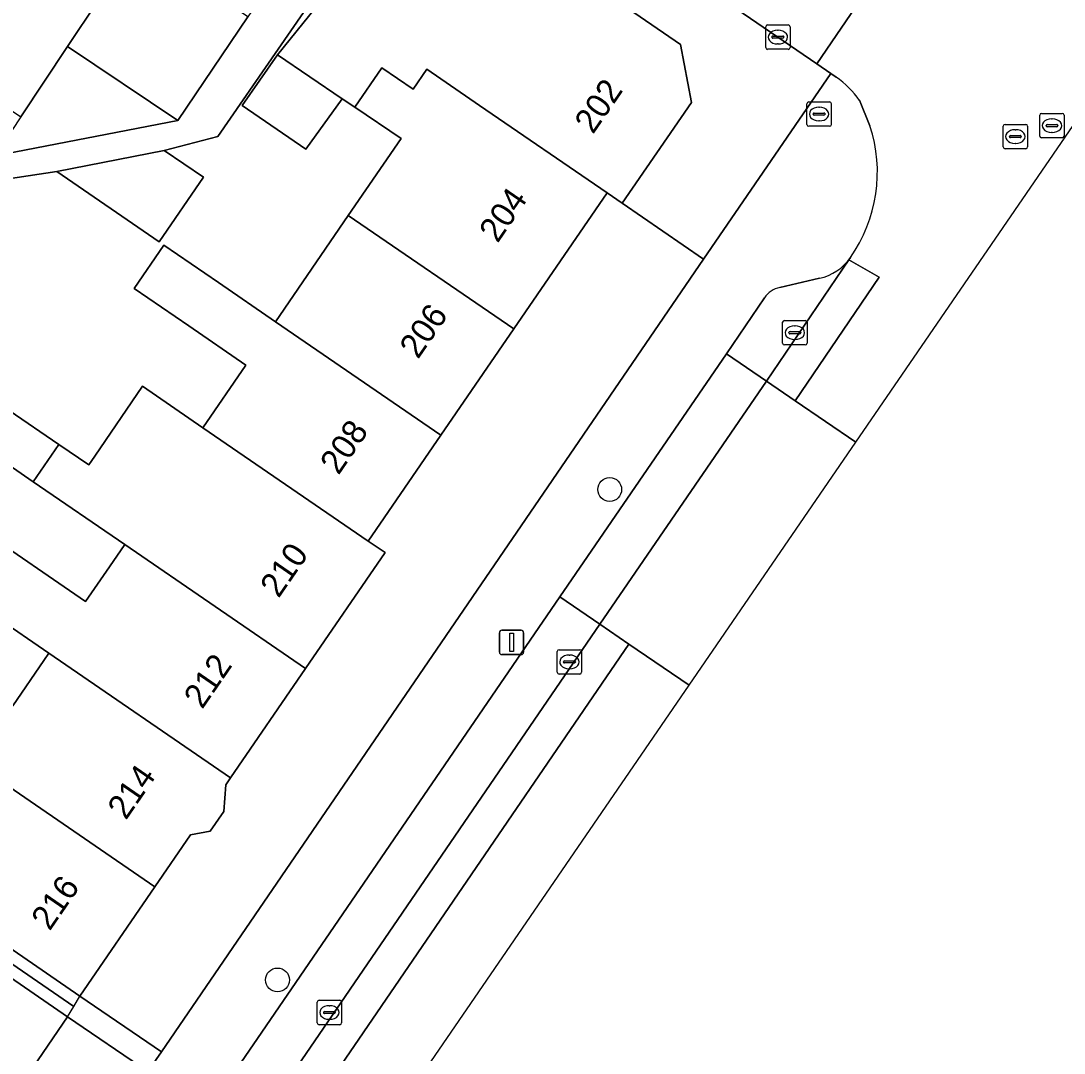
# Model space of a CAD drawing. Extents: x 159664 to 160323, y 385312 to 386115.
# Drawn here: x 160092.11 to 160134.93, y 385438.49 to 385480.85 of the extents above; entities that cross this region are included whole.
import ezdxf

# ---------------------------------------------------------------- set-up
doc = ezdxf.new("R2010")
doc.units = 0
for name, color, linetype in [('IMGEO_Boom', 7, 'Continuous'), ('IMGEO_Brandkraan', 7, 'Continuous'), ('IMGEO_Erf', 7, 'Continuous'), ('IMGEO_Kolk', 7, 'Continuous'), ('IMGEO_Lichtmast', 7, 'Continuous'), ('IMGEO_Pand', 7, 'Continuous'), ('IMGEO_Pand_nummerreeks', 7, 'Continuous'), ('IMGEO_Pand_overbouw', 7, 'Continuous'), ('IMGEO_Parkeervlak_open', 7, 'Continuous'), ('IMGEO_Rijbaan_lokaal_gesloten', 7, 'Continuous'), ('IMGEO_Rijbaan_lokaal_open', 7, 'Continuous'), ('IMGEO_Rioolput', 7, 'Continuous'), ('IMGEO_Voetpad_open', 7, 'Continuous')]:
    doc.layers.add(name, color=color, linetype=linetype)

msp = doc.modelspace()

# ---------------------------------------------------------------- linework, layer by layer
at = {"layer": 'IMGEO_Boom'}
for centre in [(160116.28, 385461.618), (160102.646, 385441.491)]:
    msp.add_circle(centre, 0.489, dxfattribs=at)
at = {"layer": 'IMGEO_Brandkraan'}
for p, q in [((160124.376, 385476.598), (160124.376, 385477.45)), ((160124.451, 385477.524), (160125.303, 385477.524)), ((160125.377, 385477.45), (160125.377, 385476.598)), ((160124.635, 385477.018), (160124.635, 385477.03)), ((160125.073, 385476.981), (160124.675, 385476.981)), ((160124.678, 385477.067), (160125.076, 385477.067)), ((160124.864, 385477.304), (160124.889, 385477.304)), ((160125.119, 385477.03), (160125.119, 385477.018)), ((160125.303, 385476.524), (160124.451, 385476.524)), ((160124.887, 385476.744), (160124.862, 385476.744))]:
    msp.add_line(p, q, dxfattribs=at)
for points in [[(160124.376, 385476.598), (160124.376, 385477.45)], [(160124.451, 385477.524), (160125.303, 385477.524)], [(160125.377, 385477.45), (160125.377, 385476.598)], [(160125.303, 385476.524), (160124.451, 385476.524)]]:
    msp.add_lwpolyline(points, dxfattribs=at)
for centre, radius, start, end in [((160124.453, 385477.448), 0.0765, 91.552, 178.448), ((160124.453, 385477.448), 0.0765, 91.552, 178.448), ((160125.301, 385477.448), 0.0765, 1.552, 88.448), ((160125.301, 385477.448), 0.0765, 1.552, 88.448), ((160124.675, 385477.027), 0.0403, 85.8775, 175.7526), ((160124.672, 385477.017), 0.0366, 178.938, 274.7102), ((160125.076, 385477.024), 0.043, 264.8664, 352.4533), ((160125.08, 385477.029), 0.0386, 1.7309, 96.639), ((160124.453, 385476.6), 0.0765, 181.552, 268.448), ((160124.453, 385476.6), 0.0765, 181.552, 268.448), ((160125.301, 385476.6), 0.0765, 271.552, 358.448), ((160125.301, 385476.6), 0.0765, 271.552, 358.448)]:
    msp.add_arc(centre, radius, start, end, dxfattribs=at)
for centre, major_axis, ratio, start_param, end_param in [((160124.863, 385477.024), (-0.387, 0.002), 0.722429, 4.712389, 7.853982), ((160124.888, 385477.024), (-0.39, 0.002), 0.717154, 1.570796, 4.712389)]:
    msp.add_ellipse(centre, major_axis=major_axis, ratio=ratio, start_param=start_param, end_param=end_param, dxfattribs=at)
at = {"layer": 'IMGEO_Erf'}
for points in [[(160095.272, 385481.662), (160090.71, 385484.694), (160091.519, 385485.911), (160089.549, 385487.221), (160090.42, 385488.53), (160087.729, 385490.367), (160084.661, 385492.46), (160083.962, 385491.435), (160082.623, 385489.472), (160084.288, 385488.335), (160084.678, 385488.927), (160086.246, 385487.894), (160084.943, 385485.918), (160089.252, 385482.91), (160087.283, 385480.142), (160092.11, 385476.904), (160094.031, 385479.795)], [(160120.131, 385471.065), (160116.798, 385473.364), (160116.172, 385473.793), (160112.341, 385468.206), (160109.353, 385463.849), (160106.372, 385459.503), (160107.06, 385459.031), (160103.796, 385454.271), (160100.72, 385449.785), (160100.525, 385449.501), (160100.44, 385448.404), (160099.89, 385447.602), (160099.078, 385447.451), (160097.614, 385445.316), (160094.537, 385440.829), (160097.88, 385438.542)], [(160097.326, 385437.733), (160094.034, 385439.985), (160090.961, 385435.505), (160087.888, 385431.024), (160084.816, 385426.545), (160081.744, 385422.066), (160085.057, 385419.799)]]:
    msp.add_lwpolyline(points, close=True, dxfattribs=at)
for points in [[(160105.155, 385483.28), (160100.197, 385476.099), (160097.997, 385475.531), (160099.604, 385474.434), (160097.786, 385471.782), (160093.588, 385474.662), (160088.142, 385473.845)], [(160091.641, 385464.862), (160093.676, 385463.466), (160094.9, 385462.626), (160095.144, 385462.982), (160097.112, 385465.852), (160099.589, 385464.154), (160101.352, 385466.723), (160099.003, 385468.334), (160096.759, 385469.873), (160097.977, 385471.647), (160100.221, 385470.109), (160102.566, 385468.503), (160105.553, 385472.86), (160107.72, 385476.019), (160105.824, 385477.303), (160105.305, 385477.655), (160103.816, 385475.587), (160101.193, 385477.369), (160102.652, 385479.452), (160105.528, 385483.033)], [(160090.421, 385460.003), (160094.77, 385457.02), (160095.751, 385458.451), (160096.375, 385459.361), (160092.625, 385461.933), (160090.59, 385463.329)], [(160091.787, 385452.746), (160093.063, 385454.606), (160093.264, 385454.898), (160088.949, 385457.857)]]:
    msp.add_lwpolyline(points, dxfattribs=at)
at = {"layer": 'IMGEO_Kolk'}
for p, q in [((160122.682, 385479.755), (160122.682, 385480.607)), ((160122.757, 385480.681), (160123.609, 385480.681)), ((160123.17, 385480.461), (160123.195, 385480.461)), ((160123.683, 385480.607), (160123.683, 385479.755)), ((160122.941, 385480.175), (160122.941, 385480.187)), ((160123.379, 385480.138), (160122.981, 385480.138)), ((160122.984, 385480.224), (160123.382, 385480.224)), ((160123.193, 385479.901), (160123.168, 385479.901)), ((160123.425, 385480.187), (160123.425, 385480.175)), ((160123.609, 385479.681), (160122.757, 385479.681)), ((160123.379, 385467.627), (160123.379, 385468.479)), ((160123.454, 385468.553), (160124.306, 385468.553)), ((160123.867, 385468.333), (160123.892, 385468.333)), ((160124.38, 385468.479), (160124.38, 385467.627)), ((160123.638, 385468.047), (160123.638, 385468.059)), ((160124.076, 385468.01), (160123.678, 385468.01)), ((160123.681, 385468.096), (160124.079, 385468.096)), ((160124.122, 385468.059), (160124.122, 385468.047)), ((160124.306, 385467.553), (160123.454, 385467.553)), ((160123.89, 385467.773), (160123.865, 385467.773)), ((160114.128, 385454.118), (160114.128, 385454.97)), ((160114.203, 385455.044), (160115.055, 385455.044)), ((160114.616, 385454.824), (160114.641, 385454.824)), ((160115.129, 385454.97), (160115.129, 385454.118)), ((160114.387, 385454.538), (160114.387, 385454.55)), ((160114.825, 385454.501), (160114.427, 385454.501)), ((160114.43, 385454.587), (160114.828, 385454.587)), ((160114.639, 385454.264), (160114.614, 385454.264)), ((160114.871, 385454.55), (160114.871, 385454.538)), ((160115.055, 385454.044), (160114.203, 385454.044)), ((160104.279, 385439.73), (160104.279, 385440.582)), ((160104.354, 385440.656), (160105.206, 385440.656)), ((160105.28, 385440.582), (160105.28, 385439.73)), ((160104.538, 385440.15), (160104.538, 385440.162)), ((160104.976, 385440.113), (160104.578, 385440.113)), ((160104.581, 385440.199), (160104.979, 385440.199)), ((160104.767, 385440.436), (160104.792, 385440.436)), ((160105.022, 385440.162), (160105.022, 385440.15)), ((160105.206, 385439.656), (160104.354, 385439.656)), ((160104.79, 385439.876), (160104.765, 385439.876))]:
    msp.add_line(p, q, dxfattribs=at)
for points in [[(160122.682, 385479.755), (160122.682, 385480.607)], [(160122.757, 385480.681), (160123.609, 385480.681)], [(160123.683, 385480.607), (160123.683, 385479.755)], [(160123.609, 385479.681), (160122.757, 385479.681)], [(160123.379, 385467.627), (160123.379, 385468.479)], [(160123.454, 385468.553), (160124.306, 385468.553)], [(160124.38, 385468.479), (160124.38, 385467.627)], [(160124.306, 385467.553), (160123.454, 385467.553)], [(160114.128, 385454.118), (160114.128, 385454.97)], [(160114.203, 385455.044), (160115.055, 385455.044)], [(160115.129, 385454.97), (160115.129, 385454.118)], [(160115.055, 385454.044), (160114.203, 385454.044)], [(160104.279, 385439.73), (160104.279, 385440.582)], [(160104.354, 385440.656), (160105.206, 385440.656)], [(160105.28, 385440.582), (160105.28, 385439.73)], [(160105.206, 385439.656), (160104.354, 385439.656)]]:
    msp.add_lwpolyline(points, dxfattribs=at)
for centre, radius, start, end in [((160122.759, 385480.605), 0.0765, 91.552, 178.448), ((160122.759, 385480.605), 0.0765, 91.552, 178.448), ((160123.607, 385480.605), 0.0765, 1.552, 88.448), ((160123.607, 385480.605), 0.0765, 1.552, 88.448), ((160122.981, 385480.184), 0.0403, 85.8775, 175.7526), ((160122.978, 385480.174), 0.0366, 178.938, 274.7102), ((160123.382, 385480.181), 0.043, 264.8664, 352.4533), ((160123.386, 385480.186), 0.0386, 1.7309, 96.639), ((160122.759, 385479.757), 0.0765, 181.552, 268.448), ((160122.759, 385479.757), 0.0765, 181.552, 268.448), ((160123.607, 385479.757), 0.0765, 271.552, 358.448), ((160123.607, 385479.757), 0.0765, 271.552, 358.448), ((160123.456, 385468.477), 0.0765, 91.552, 178.448), ((160123.456, 385468.477), 0.0765, 91.552, 178.448), ((160124.304, 385468.477), 0.0765, 1.552, 88.448), ((160124.304, 385468.477), 0.0765, 1.552, 88.448), ((160123.678, 385468.056), 0.0403, 85.8775, 175.7526), ((160123.675, 385468.046), 0.0366, 178.938, 274.7102), ((160124.079, 385468.053), 0.043, 264.8664, 352.4533), ((160124.083, 385468.058), 0.0386, 1.7309, 96.639), ((160123.456, 385467.629), 0.0765, 181.552, 268.448), ((160123.456, 385467.629), 0.0765, 181.552, 268.448), ((160124.304, 385467.629), 0.0765, 271.552, 358.448), ((160124.304, 385467.629), 0.0765, 271.552, 358.448), ((160114.205, 385454.968), 0.0765, 91.552, 178.448), ((160114.205, 385454.968), 0.0765, 91.552, 178.448), ((160115.053, 385454.968), 0.0765, 1.552, 88.448), ((160115.053, 385454.968), 0.0765, 1.552, 88.448), ((160114.427, 385454.547), 0.0403, 85.8775, 175.7526), ((160114.424, 385454.537), 0.0366, 178.938, 274.7102), ((160114.828, 385454.544), 0.043, 264.8664, 352.4533), ((160114.832, 385454.549), 0.0386, 1.7309, 96.639), ((160114.205, 385454.12), 0.0765, 181.552, 268.448), ((160114.205, 385454.12), 0.0765, 181.552, 268.448), ((160115.053, 385454.12), 0.0765, 271.552, 358.448), ((160115.053, 385454.12), 0.0765, 271.552, 358.448), ((160104.356, 385440.58), 0.0765, 91.552, 178.448), ((160104.356, 385440.58), 0.0765, 91.552, 178.448), ((160105.204, 385440.58), 0.0765, 1.552, 88.448), ((160105.204, 385440.58), 0.0765, 1.552, 88.448), ((160104.578, 385440.159), 0.0403, 85.8775, 175.7526), ((160104.575, 385440.149), 0.0366, 178.938, 274.7102), ((160104.979, 385440.156), 0.043, 264.8664, 352.4533), ((160104.983, 385440.161), 0.0386, 1.7309, 96.639), ((160104.356, 385439.732), 0.0765, 181.552, 268.448), ((160104.356, 385439.732), 0.0765, 181.552, 268.448), ((160105.204, 385439.732), 0.0765, 271.552, 358.448), ((160105.204, 385439.732), 0.0765, 271.552, 358.448)]:
    msp.add_arc(centre, radius, start, end, dxfattribs=at)
for centre, major_axis, ratio, start_param, end_param in [((160123.169, 385480.181), (-0.387, 0.002), 0.722429, 4.712389, 7.853982), ((160123.194, 385480.181), (-0.39, 0.002), 0.717154, 1.570796, 4.712389), ((160123.866, 385468.053), (-0.387, 0.002), 0.722429, 4.712389, 7.853982), ((160123.891, 385468.053), (-0.39, 0.002), 0.717154, 1.570796, 4.712389), ((160114.615, 385454.544), (-0.387, 0.002), 0.722429, 4.712389, 7.853982), ((160114.64, 385454.544), (-0.39, 0.002), 0.717154, 1.570796, 4.712389), ((160104.766, 385440.156), (-0.387, 0.002), 0.722429, 4.712389, 7.853982), ((160104.791, 385440.156), (-0.39, 0.002), 0.717154, 1.570796, 4.712389)]:
    msp.add_ellipse(centre, major_axis=major_axis, ratio=ratio, start_param=start_param, end_param=end_param, dxfattribs=at)
at = {"layer": 'IMGEO_Lichtmast'}
for p, q in [((160111.757, 385454.941), (160111.757, 385455.741)), ((160111.757, 385455.741), (160111.757, 385454.941)), ((160111.857, 385455.841), (160112.647, 385455.841)), ((160112.647, 385455.841), (160111.857, 385455.841)), ((160112.747, 385455.741), (160112.747, 385454.941)), ((160112.747, 385454.941), (160112.747, 385455.741)), ((160112.647, 385454.841), (160111.857, 385454.841)), ((160111.857, 385454.841), (160112.647, 385454.841))]:
    msp.add_line(p, q, dxfattribs=at)
msp.add_lwpolyline([(160112.177, 385455.716), (160112.327, 385455.716), (160112.327, 385454.966), (160112.177, 385454.966), (160112.177, 385455.716)], dxfattribs=at)
for centre, start, end in [((160111.857, 385455.741), 90, 180), ((160111.857, 385455.741), 90, 180), ((160112.647, 385455.741), 0, 90), ((160112.647, 385455.741), 360, 90), ((160111.857, 385454.941), 180, 270), ((160111.857, 385454.941), 180, 270), ((160112.647, 385454.941), 270, 0), ((160112.647, 385454.941), 270, 0)]:
    msp.add_arc(centre, 0.1, start, end, dxfattribs=at)
at = {"layer": 'IMGEO_Pand'}
for points in [[(160119.187, 385479.884), (160108.429, 385487.262), (160105.601, 385483.139), (160105.528, 385483.033), (160102.652, 385479.452), (160105.305, 385477.655), (160105.824, 385477.303), (160106.935, 385478.924), (160108.219, 385478.044), (160108.779, 385478.861), (160110.94, 385477.38), (160116.172, 385473.793), (160116.798, 385473.364), (160119.632, 385477.496)], [(160101.434, 385481.016), (160096.899, 385484.11), (160095.272, 385481.662), (160094.031, 385479.795), (160098.556, 385476.767)], [(160094.031, 385479.795), (160092.11, 385476.904), (160091.052, 385475.312), (160098.556, 385476.767)], [(160102.652, 385479.452), (160101.193, 385477.369), (160103.816, 385475.587), (160105.305, 385477.655)], [(160116.172, 385473.793), (160110.94, 385477.38), (160108.779, 385478.861), (160108.219, 385478.044), (160106.935, 385478.924), (160105.824, 385477.303), (160107.72, 385476.019), (160105.553, 385472.86), (160112.341, 385468.206)], [(160099.604, 385474.434), (160097.997, 385475.531), (160093.588, 385474.662), (160097.786, 385471.782)], [(160109.353, 385463.849), (160112.341, 385468.206), (160105.553, 385472.86), (160102.566, 385468.503)], [(160102.566, 385468.503), (160100.221, 385470.109), (160097.977, 385471.647), (160096.759, 385469.873), (160099.003, 385468.334), (160101.352, 385466.723), (160099.589, 385464.154), (160106.372, 385459.503), (160109.353, 385463.849)], [(160099.589, 385464.154), (160097.112, 385465.852), (160095.144, 385462.982), (160094.9, 385462.626), (160093.676, 385463.466), (160092.625, 385461.933), (160096.375, 385459.361), (160103.796, 385454.271), (160107.06, 385459.031), (160106.372, 385459.503)], [(160093.676, 385463.466), (160091.641, 385464.862), (160090.59, 385463.329), (160092.625, 385461.933)], [(160096.375, 385459.361), (160095.751, 385458.451), (160094.77, 385457.02), (160090.421, 385460.003), (160088.949, 385457.857), (160093.264, 385454.898), (160100.72, 385449.785), (160103.796, 385454.271)], [(160093.264, 385454.898), (160093.063, 385454.606), (160091.787, 385452.746), (160087.44, 385455.728), (160087.188, 385455.36), (160085.838, 385453.392), (160097.614, 385445.316), (160099.078, 385447.451), (160099.89, 385447.602), (160100.44, 385448.404), (160100.525, 385449.501), (160100.72, 385449.785)], [(160085.838, 385453.392), (160084.279, 385451.118), (160088.656, 385448.117), (160087.138, 385445.903), (160090.414, 385443.657), (160094.537, 385440.829), (160097.614, 385445.316)], [(160089.911, 385442.813), (160086.575, 385445.1), (160084.995, 385442.797), (160082.381, 385444.589), (160080.89, 385442.415), (160090.961, 385435.505), (160094.034, 385439.985)]]:
    msp.add_lwpolyline(points, close=True, dxfattribs=at)
at = {"layer": 'IMGEO_Pand_overbouw'}
for points in [[(160087.138, 385445.903), (160086.856, 385445.502), (160094.286, 385440.407), (160094.537, 385440.829), (160090.414, 385443.657)], [(160094.034, 385439.985), (160094.286, 385440.407), (160086.856, 385445.502), (160086.575, 385445.1), (160089.911, 385442.813)]]:
    msp.add_lwpolyline(points, close=True, dxfattribs=at)
at = {"layer": 'IMGEO_Parkeervlak_open'}
for points in [[(160122.635, 385469.488), (160121.077, 385467.191), (160122.716, 385466.066), (160126.097, 385471.044)], [(160126.097, 385471.044), (160126.161, 385471.137)], [(160124.886, 385470.286), (160123.262, 385469.907)]]:
    msp.add_lwpolyline(points, dxfattribs=at)
for points in [[(160115.877, 385456.089), (160122.716, 385466.066), (160121.077, 385467.191), (160114.229, 385457.219)], [(160115.877, 385456.089), (160114.229, 385457.219), (160068.3, 385390.129), (160069.959, 385388.996)]]:
    msp.add_lwpolyline(points, close=True, dxfattribs=at)
for centre, radius, start, end in [((160124.438, 385472.337), 2.099, 282.3079, 325.1344), ((160123.464, 385468.925), 1.002, 101.6527, 145.8539)]:
    msp.add_arc(centre, radius, start, end, dxfattribs=at)
at = {"layer": 'IMGEO_Rijbaan_lokaal_gesloten'}
for points in [[(160126.386, 385463.557), (160177.149, 385537.53), (160174.591, 385539.295), (160136.26, 385483.38), (160135.072, 385484.188)], [(160127.579, 385483.19), (160124.777, 385479.087), (160125.358, 385478.69), (160125.579, 385478.539)], [(160126.537, 385477.588), (160126.961, 385476.547)], [(160126.161, 385471.137), (160126.097, 385471.044), (160127.34, 385470.33), (160123.89, 385465.263), (160126.386, 385463.557)]]:
    msp.add_lwpolyline(points, dxfattribs=at)
for points in [[(160126.097, 385471.044), (160122.716, 385466.066), (160123.89, 385465.263), (160127.34, 385470.33)], [(160117.063, 385455.278), (160115.877, 385456.089), (160069.959, 385388.996), (160071.159, 385388.157), (160083.1, 385405.61)], [(160073.515, 385386.51), (160107.657, 385436.264), (160119.541, 385453.582), (160117.063, 385455.278), (160083.1, 385405.61), (160071.159, 385388.157)]]:
    msp.add_lwpolyline(points, close=True, dxfattribs=at)
for centre, radius, start, end in [((160123.071, 385475.054), 4.293, 36.1652, 54.255), ((160121.165, 385474.64), 6.102, 324.9636, 18.2131)]:
    msp.add_arc(centre, radius, start, end, dxfattribs=at)
at = {"layer": 'IMGEO_Rijbaan_lokaal_open'}
for points in [[(160103.091, 385500), (160091.569, 385507.857), (160085.143, 385512.247), (160082.355, 385508.121), (160094.215, 385500), (160109.484, 385489.552), (160124.777, 385479.087), (160127.579, 385483.19), (160111.385, 385494.315), (160108.508, 385496.287)], [(160119.541, 385453.582), (160126.386, 385463.557), (160123.89, 385465.263), (160122.716, 385466.066), (160115.877, 385456.089), (160117.063, 385455.278)]]:
    msp.add_lwpolyline(points, close=True, dxfattribs=at)
at = {"layer": 'IMGEO_Rioolput'}
for p, q in [((160133.93, 385476.124), (160133.93, 385476.976)), ((160134.005, 385477.05), (160134.857, 385477.05)), ((160134.931, 385476.976), (160134.931, 385476.124)), ((160132.431, 385475.676), (160132.431, 385476.528)), ((160132.506, 385476.602), (160133.358, 385476.602)), ((160133.432, 385476.528), (160133.432, 385475.676)), ((160134.189, 385476.544), (160134.189, 385476.556)), ((160134.627, 385476.507), (160134.229, 385476.507)), ((160134.232, 385476.593), (160134.63, 385476.593)), ((160134.418, 385476.83), (160134.443, 385476.83)), ((160134.673, 385476.556), (160134.673, 385476.544)), ((160132.69, 385476.096), (160132.69, 385476.108)), ((160133.128, 385476.059), (160132.73, 385476.059)), ((160132.733, 385476.145), (160133.131, 385476.145)), ((160132.919, 385476.382), (160132.944, 385476.382)), ((160133.174, 385476.108), (160133.174, 385476.096)), ((160134.857, 385476.05), (160134.005, 385476.05)), ((160134.441, 385476.27), (160134.416, 385476.27)), ((160132.942, 385475.822), (160132.917, 385475.822)), ((160133.358, 385475.602), (160132.506, 385475.602))]:
    msp.add_line(p, q, dxfattribs=at)
for points in [[(160133.93, 385476.124), (160133.93, 385476.976)], [(160134.005, 385477.05), (160134.857, 385477.05)], [(160134.931, 385476.976), (160134.931, 385476.124)], [(160132.431, 385475.676), (160132.431, 385476.528)], [(160132.506, 385476.602), (160133.358, 385476.602)], [(160133.432, 385476.528), (160133.432, 385475.676)], [(160134.857, 385476.05), (160134.005, 385476.05)], [(160133.358, 385475.602), (160132.506, 385475.602)]]:
    msp.add_lwpolyline(points, dxfattribs=at)
for centre, radius, start, end in [((160134.007, 385476.974), 0.0765, 91.552, 178.448), ((160134.007, 385476.974), 0.0765, 91.552, 178.448), ((160134.855, 385476.974), 0.0765, 1.552, 88.448), ((160134.855, 385476.974), 0.0765, 1.552, 88.448), ((160132.508, 385476.526), 0.0765, 91.552, 178.448), ((160132.508, 385476.526), 0.0765, 91.552, 178.448), ((160133.356, 385476.526), 0.0765, 1.552, 88.448), ((160133.356, 385476.526), 0.0765, 1.552, 88.448), ((160134.229, 385476.553), 0.0403, 85.8775, 175.7526), ((160134.226, 385476.543), 0.0366, 178.938, 274.7102), ((160134.63, 385476.55), 0.043, 264.8664, 352.4533), ((160134.634, 385476.555), 0.0386, 1.7309, 96.639), ((160132.73, 385476.105), 0.0403, 85.8775, 175.7526), ((160132.727, 385476.095), 0.0366, 178.938, 274.7102), ((160133.131, 385476.102), 0.043, 264.8664, 352.4533), ((160133.135, 385476.107), 0.0386, 1.7309, 96.639), ((160134.007, 385476.126), 0.0765, 181.552, 268.448), ((160134.007, 385476.126), 0.0765, 181.552, 268.448), ((160134.855, 385476.126), 0.0765, 271.552, 358.448), ((160134.855, 385476.126), 0.0765, 271.552, 358.448), ((160132.508, 385475.678), 0.0765, 181.552, 268.448), ((160132.508, 385475.678), 0.0765, 181.552, 268.448), ((160133.356, 385475.678), 0.0765, 271.552, 358.448), ((160133.356, 385475.678), 0.0765, 271.552, 358.448)]:
    msp.add_arc(centre, radius, start, end, dxfattribs=at)
for centre, major_axis, ratio, start_param, end_param in [((160134.417, 385476.55), (-0.387, 0.002), 0.722429, 4.712389, 7.853982), ((160134.442, 385476.55), (-0.39, 0.002), 0.717154, 1.570796, 4.712389), ((160132.918, 385476.102), (-0.387, 0.002), 0.722429, 4.712389, 7.853982), ((160132.943, 385476.102), (-0.39, 0.002), 0.717154, 1.570796, 4.712389)]:
    msp.add_ellipse(centre, major_axis=major_axis, ratio=ratio, start_param=start_param, end_param=end_param, dxfattribs=at)
at = {"layer": 'IMGEO_Voetpad_open'}
for points in [[(160090.729, 385499.463), (160092.771, 385497.951), (160094.924, 385496.601), (160094.877, 385496.532), (160094.459, 385495.911), (160097.019, 385494.185), (160099.01, 385492.843), (160099.462, 385493.504), (160102.069, 385491.725), (160101.615, 385491.059), (160103.055, 385490.076), (160103.51, 385490.743), (160106.622, 385488.619), (160108.083, 385487.522), (160108.429, 385487.262), (160119.187, 385479.884), (160119.632, 385477.496), (160116.798, 385473.364), (160120.131, 385471.065), (160125.358, 385478.69), (160124.777, 385479.087), (160109.484, 385489.552), (160094.215, 385500), (160082.355, 385508.121)], [(160088.142, 385473.845), (160093.588, 385474.662), (160097.997, 385475.531), (160100.197, 385476.099), (160105.155, 385483.28), (160108.083, 385487.522), (160106.622, 385488.619), (160103.804, 385484.489), (160103.684, 385484.314), (160101.434, 385481.016), (160098.556, 385476.767), (160091.052, 385475.312)], [(160125.579, 385478.539), (160125.358, 385478.69), (160120.131, 385471.065), (160097.88, 385438.542), (160097.326, 385437.733), (160085.057, 385419.799), (160084.51, 385419.001), (160066.005, 385391.953), (160065.508, 385391.227), (160053.007, 385372.955), (160052.525, 385372.25), (160043.184, 385358.597), (160041.586, 385356.262), (160038.222, 385351.416), (160034.072, 385345.486), (160024.043, 385330.992), (160022.199, 385331.074), (160024.444, 385328.62)], [(160126.961, 385476.547), (160126.537, 385477.588)], [(160123.262, 385469.907), (160124.886, 385470.286)], [(160121.077, 385467.191), (160122.635, 385469.488)], [(160044.981, 385356.152), (160058.121, 385375.356), (160068.3, 385390.129), (160114.229, 385457.219), (160121.077, 385467.191)]]:
    msp.add_lwpolyline(points, dxfattribs=at)
msp.add_lwpolyline([(160090.414, 385443.657), (160087.138, 385445.903), (160078.966, 385451.522), (160075.89, 385453.63), (160078.183, 385456.968), (160081.805, 385462.243), (160080.864, 385462.885), (160080.735, 385462.973), (160079.4, 385461.014), (160071.2, 385449.087), (160072.185, 385448.418), (160075.18, 385452.815), (160075.465, 385452.621), (160078.949, 385450.216), (160086.575, 385445.1), (160089.911, 385442.813), (160094.034, 385439.985), (160097.326, 385437.733), (160097.88, 385438.542), (160094.537, 385440.829)], close=True, dxfattribs=at)
for centre, radius, start, end in [((160123.071, 385475.054), 4.293, 36.1652, 54.255), ((160121.165, 385474.64), 6.102, 324.9636, 18.2131), ((160124.438, 385472.337), 2.099, 282.3079, 325.1344), ((160123.464, 385468.925), 1.002, 101.6527, 145.8539)]:
    msp.add_arc(centre, radius, start, end, dxfattribs=at)

# ---------------------------------------------------------------- texts
at = {"layer": 'IMGEO_Pand_nummerreeks'}
for s, rotation, p in [('202', 55.554, (160115.595, 385476.166)), ('204', 55.5597, (160111.68, 385471.699)), ('206', 55.5579, (160108.414, 385466.936)), ('208', 55.5579, (160105.15, 385462.176)), ('210', 55.4738, (160102.691, 385457.126)), ('212', 55.4738, (160099.557, 385452.571)), ('214', 55.4738, (160096.428, 385448.022)), ('216', 55.472, (160093.297, 385443.472))]:
    msp.add_text(s, height=1, rotation=rotation, dxfattribs=at).set_placement(p)

doc.saveas('drawing.dxf')
